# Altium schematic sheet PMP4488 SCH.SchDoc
size 431 x 279 mm; Date: Not shown in title block; ApprovedBy: Not shown in title block; CheckedBy: Not shown in title block; Author: Not shown in title block; CompanyName: Not shown in title block; Engineer: David Ji; Organization: Not shown in title block; Address1: Not shown in title block; Address2: Not shown in title block; Address3: Not shown in title block; Address4: Not shown in title block; DocumentNumber: 1; Revision: Use project parameter SCH_Rev; SheetNumber: 1; SheetTotal: 1; PageSetup: Record=PageOptions¦CenterHorizontal=True¦CenterVertical=True¦PrintScale=1.00¦XCorrection=1.00¦YCorrection=1.00¦PrintKind=0¦BorderSize=5000000¦LeftOffset=0¦BottomOffset=0¦Orientation=2¦PaperLength=1000¦PaperWidth=1000¦Scale=100¦PaperSource=15¦PrintQuality=600¦MediaType=1¦DitherType=10¦PaperKind=Letter¦PrintScaleMode=1
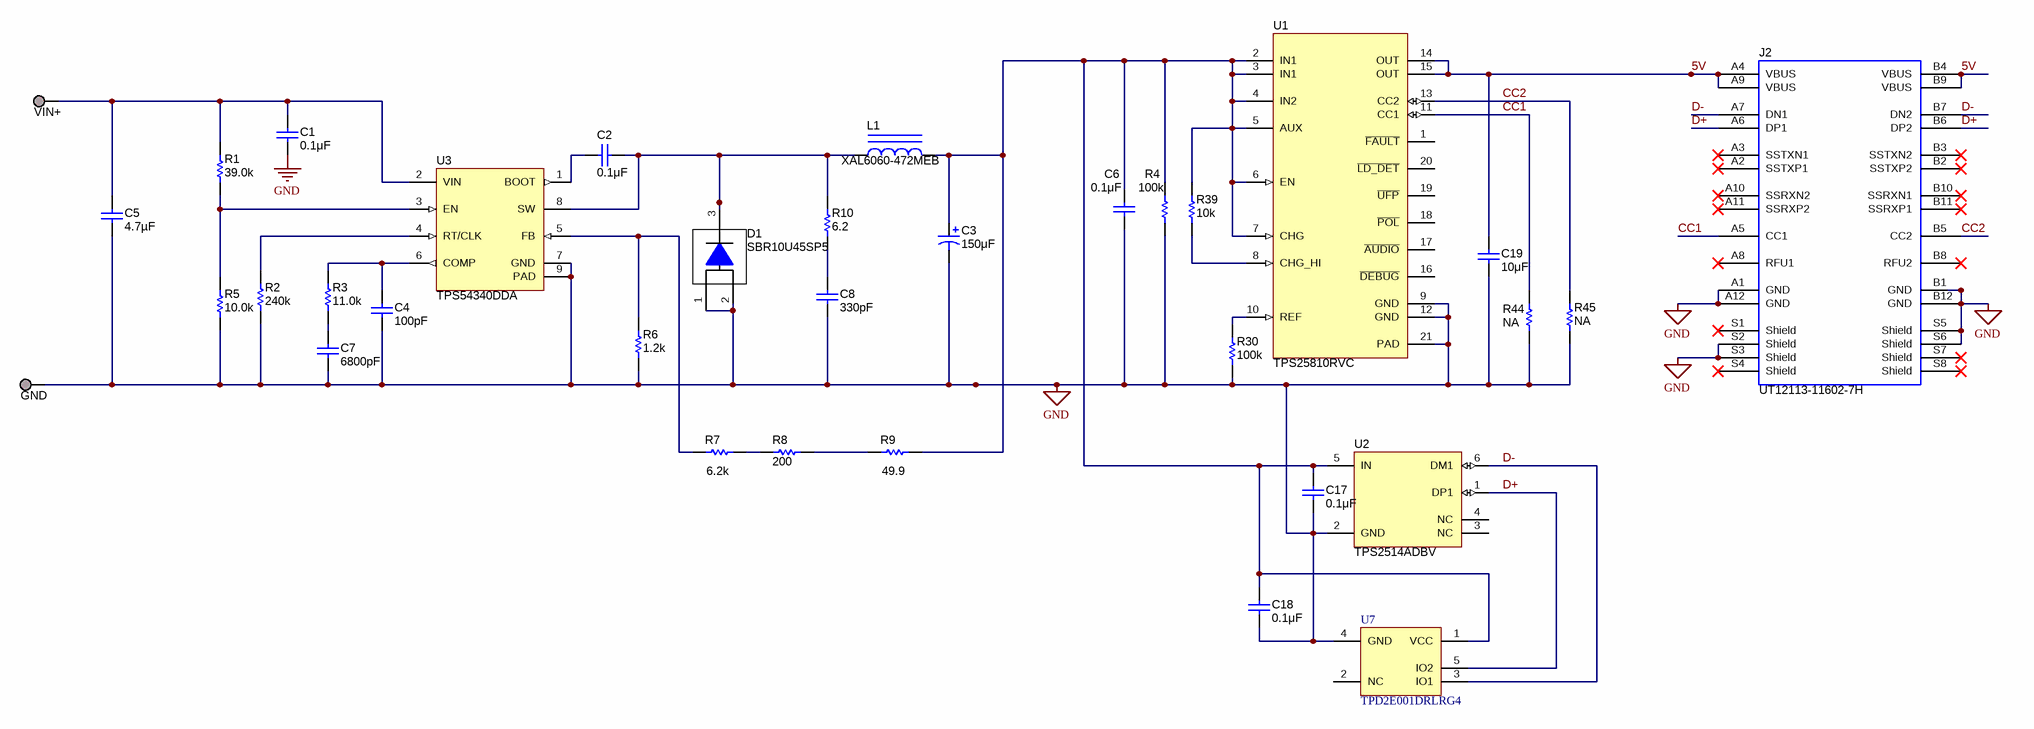
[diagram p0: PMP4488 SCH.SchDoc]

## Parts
C1  ValueDisplayed: 0.1μF  [0603]  (hidden comment: C0603C104K5RACTU)
C2  ValueDisplayed: 0.1μF  [0603]  (hidden comment: C0603C104K5RACTU)
C3  ValueDisplayed: 150μF  [CAPAE_SP-Cap_Standard]  (hidden comment: EEFCX0J181R)
C4  ValueDisplayed: 100pF  [0603]  (hidden comment: GRM1885C1H101JA01D)
C5  ValueDisplayed: 4.7µF  [1206]  (hidden comment: GRM319R61H475KA12)
C6  ValueDisplayed: 0.1μF  [0603]  (hidden comment: C1608X7R1E104K)
C7  ValueDisplayed: 6800pF  [0603]  (hidden comment: GRM188R71H682KA01D)
C8  ValueDisplayed: 330pF  [0603]  (hidden comment: GRM188R71H331KA01D)
C17  ValueDisplayed: 0.1μF  [0603]  (hidden comment: 06033C104JAT2A)
C18  ValueDisplayed: 0.1μF  [0603]  (hidden comment: 06033C104JAT2A)
C19  ValueDisplayed: 10μF  [0805_HV]  (hidden comment: C0805C106K8PACTU)
D1  SBR10U45SP5  [PowerDI5]
GND  Suggest using a net name here  [Keystone1502-2]  (value not drawn)
J2  UT12113-11602-7H  [Foxconn_UT12113-11602-7H]
L1  XAL6060-472MEB  [XAL6060]
R1  ValueDisplayed: 39.0k  [0603]  (hidden comment: RC0603FR-0739KL)
R2  ValueDisplayed: 240k  [0603]  (hidden comment: RC0603FR-07240KL)
R3  ValueDisplayed: 11.0k  [0603]  (hidden comment: RC0603FR-0711KL)
R4  ValueDisplayed: 100k  [0603]  (hidden comment: CRCW0603100KJNEA)
R5  ValueDisplayed: 10.0k  [0603]  (hidden comment: RC0603FR-0710KL)
R6  ValueDisplayed: 1.2k  [0603]  (hidden comment: CRCW06031K21FKEA)
R7  ValueDisplayed: 6.2k  [0603]  (hidden comment: RC0603FR-078K25L)
R8  ValueDisplayed: 200  [0603]  (hidden comment: RC0603FR-07200RL)
R9  ValueDisplayed: 49.9  [0603]  (hidden comment: RC0603FR-0749R9L)
R10  ValueDisplayed: 6.2  [0805_HV]  (hidden comment: CRCW08056R20JNEA)
R30  ValueDisplayed: 100k  [0603]  (hidden comment: CRCW0603100KFKEA)
R39  ValueDisplayed: 10k  [0603]  (hidden comment: CRCW060310K0JNEA)
R44  ValueDisplayed: NA  [0603]  (hidden comment: CRCW060310K0JNEA)
R45  ValueDisplayed: NA  [0603]  (hidden comment: CRCW060310K0JNEA)
U1  TPS25810RVC  [RVC0020A]
U2  TPS2514ADBV  [DBV0006A_N]
U3  TPS54340DDA  [DDA0008E_N]
U7  TPD2E001DRLRG4  [DRL0005A]
VIN+  Suggest using a net name here  [Keystone1502-2]  (value not drawn)

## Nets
GND: C1.2 C3.2(-) C4.2 C5.2 C6.2 C7.2 C8.1 C17.2 C18.2 C19.2 D1.1(A) D1.2(A) GND.1 J2.A1(GND) J2.A12(GND) J2.B1(GND) J2.B12(GND) J2.S2(Shield) J2.S3(Shield) J2.S5(Shield) J2.S6(Shield) R2.1 R4.1 R5.1 R6.1 R30.1 R44.1 R45.1 U1.9(GND) U1.12(GND) U1.21(PAD) U2.2(GND) U3.7(GND) U3.9(PAD) U7.4(GND)
5V: C19.1 J2.A4(VBUS) J2.A9(VBUS) J2.B4(VBUS) J2.B9(VBUS) U1.14(OUT) U1.15(OUT)
CC1: J2.A5(CC1) R44.2 U1.11(CC1)
CC2: J2.B5(CC2) R45.2 U1.13(CC2)
D+: J2.A6(DP1) J2.B6(DP2) U2.1(DP1) U7.5(IO2)
D-: J2.A7(DN1) J2.B7(DN2) U2.6(DM1) U7.3(IO1)
NetC1_1: C1.1 C5.1 R1.2 U3.2(VIN) VIN+.1
NetC2_1: C2.1 U3.1(BOOT)
NetC2_2: C2.2 D1.3(K) L1.1 R10.2 U3.8(SW)
NetC3_1: C3.1(+) C6.1 C17.1 C18.1 L1.2 R4.2 R9.2 R39.2 U1.2(IN1) U1.3(IN1) U1.4(IN2) U1.5(AUX) U1.6(EN) U1.7(CHG) U2.5(IN) U7.1(VCC)
NetC4_1: C4.1 R3.2 U3.6(COMP)
NetC7_1: C7.1 R3.1
NetC8_2: C8.2 R10.1
NetR1_1: R1.1 R5.2 U3.3(EN)
NetR2_2: R2.2 U3.4(RT/CLK)
NetR6_2: R6.2 R7.1 U3.5(FB)
NetR7_2: R7.2 R8.1
NetR8_2: R8.2 R9.1
NetR30_2: R30.2 U1.10(REF)
NetR39_1: R39.1 U1.8(CHG_HI)

Not connected (* = marked no-connect by the designer): J2 A2(SSTXP1)* A3(SSTXN1)* A8(RFU1)* A10(SSRXN2)* A11(SSRXP2)* B2(SSTXP2)* B3(SSTXN2)* B8(RFU2)* B10(SSRXN1)* B11(SSRXP1)* S1(Shield)* S4(Shield)* S7(Shield)* S8(Shield)*; U1 1(~{FAULT}) 16(~{DEBUG}) 17(~{AUDIO}) 18(~{POL}) 19(~{UFP}) 20(~{LD_DET}); U2 3(NC) 4(NC); U7 2(NC)

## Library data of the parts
C1 C2 = C0603C104K5RACTU: CAP, CERM, 0.1 μF, 50 V, +/- 10%, X7R, 0603; Manufacturer: Kemet; Polarized: N; CompType: Capacitor; Value: 0.1uF; U/M: EA; Cap_F: 0.0000001; Tolerance_%: 10; Value1: Unknown; VDC_V: 50; Value2: 50V; TaMin_C: -55; TaMax_C: 125
C3 = EEFCX0J181R: CAP, AL, 150 μF, 6.3 V, +/- 20%, 15 ohm, SMD; Manufacturer: Panasonic; Polarized: Y; CompType: Capacitor; Value: 180uF; U/M: EA; Cap_F: 0.00018; Tolerance_%: 20; Value1: 15 ohm; VDC_V: 6.3; Value2: 6.3V; ESR_ohm: 15; IRMS_A: 2.7; TaMin_C: -40; TaMax_C: 105
C4 = GRM1885C1H101JA01D: CAP, CERM, 100 pF, 50 V, +/- 5%, C0G/NP0, 0603; Manufacturer: MuRata; Polarized: N; CompType: Capacitor; Value: 100pF; U/M: EA; Cap_F: 0.0000000001; Tolerance_%: 5; Value1: Unknown; VDC_V: 50; Value2: 50V; TaMin_C: -55; TaMax_C: 125
C5 = GRM319R61H475KA12: CAP, CERM, 4.7 µF, 50 V, +/- 10%, X5R, 1206; Manufacturer: MuRata; Polarized: N; CompType: Capacitor; Value: 4.7uF; U/M: EA; Cap_F: 0.0000047; Tolerance_%: 10; Value1: Unknown; VDC_V: 50; Value2: 50V; TaMin_C: -55; TaMax_C: 85
C6 = C1608X7R1E104K: CAP, CERM, 0.1 μF, 25 V, +/- 10%, X7R, 0603; Manufacturer: TDK; Polarized: N; CompType: Capacitor; Value: 0.1uF; U/M: EA; Cap_F: 0.0000001; Tolerance_%: 10; ESR_ohm: 0.017; Value1: 0.017 ohm; VDC_V: 25; Value2: 25V; TaMin_C: -55; TaMax_C: 125
C7 = GRM188R71H682KA01D: CAP, CERM, 6800 pF, 50 V, +/- 10%, X7R, 0603; Manufacturer: MuRata; Polarized: N; CompType: Capacitor; Value: 6800pF; U/M: EA; Cap_F: 0.0000000068; Tolerance_%: 10; Value1: Unknown; VDC_V: 50; Value2: 50V; TaMin_C: -55; TaMax_C: 125
C8 = GRM188R71H331KA01D: CAP, CERM, 330 pF, 50 V, +/- 10%, X7R, 0603; Manufacturer: MuRata; Polarized: N; CompType: Capacitor; Value: 330pF; U/M: EA; Cap_F: 0.00000000033; Tolerance_%: 10; Value1: Unknown; VDC_V: 50; Value2: 50V; TaMin_C: -55; TaMax_C: 125
C17 C18 = 06033C104JAT2A: CAP, CERM, 0.1 μF, 25 V, +/- 5%, X7R, 0603; Manufacturer: AVX; Polarized: N; CompType: Capacitor; Value: 0.1uF; U/M: EA; Cap_F: 0.0000001; Tolerance_%: 5; ESR_ohm: 0.05; Value1: 0.05 ohm; VDC_V: 25; Value2: 25V; TaMin_C: -55; TaMax_C: 125
C19 = C0805C106K8PACTU: CAP, CERM, 10 μF, 10 V, +/- 10%, X5R, 0805; Manufacturer: Kemet; Polarized: N; CompType: Capacitor; Value: 10uF; U/M: EA; Cap_F: 0.00001; Tolerance_%: 10; ESR_ohm: 0.003; Value1: 0.003 ohm; Value2: 10V; IRMS_A: 11.43; TaMin_C: -55; TaMax_C: 85; Cap_Case: 0805
D1 = SBR10U45SP5: Diode, Super Barrier Rectifier, 45 V, 10 A, PowerDI5; Manufacturer: Diodes Inc.; SymbolCreator: a0412235; U/M: EA; Vf_V: 0.47; Value: 45V; Value1: 10A; Value2: 0.47V; Io_A: 10; Vr_V: 45; TJmax_C: 150
GND VIN+ = 1502-2: Terminal, Turret, TH, Double; Manufacturer: Keystone; CompType: Turret Terminal; U/M: EA
J2 = UT12113-11602-7H: Connector, Receptacle, USB TYPE C, R/A, SMT; Manufacturer: Foxconn; SymbolCreator: Altium; U/M: EA
L1 = XAL6060-472MEB: Inductor, Shielded, Composite, 4.7 µH, 10.5 A, 0.015 ohm, SMD; Manufacturer: Coilcraft; Value: 4.7uH; Ind_H: 4.7E-6; ValueDisplayed: 4.7µH; Imax_A: 10.5; Irms: 12.3A @ 40C rise; Isat: 10.5A @ 30% inductance drop; DCR_ohm: 0.015; Value2: 10.5A
R1 = RC0603FR-0739KL: RES, 39.0 k, 1%, 0.1 W, 0603; Manufacturer: Yageo America; CompType: Resistor; Value: 39.0k; Res_ohm: 39000; Value_Code: 39k0; Tolerance_%: 1; Power_W: 0.1; Value2: 0.1W; VDC_V: 150; TempCo: 200 ppm/C; U/M: EA
R2 = RC0603FR-07240KL: RES, 240 k, 1%, 0.1 W, 0603; Manufacturer: Yageo America; CompType: Resistor; Value: 240k; Res_ohm: 240000; Tolerance_%: 1; Power_W: 0.1; Value2: 0.1W; VDC_V: 150; TempCo: 200 ppm/C; U/M: EA
R3 = RC0603FR-0711KL: RES, 11.0 k, 1%, 0.1 W, 0603; Manufacturer: Yageo America; CompType: Resistor; Value: 11.0k; Res_ohm: 11000; Value_Code: 11k0; Tolerance_%: 1; Power_W: 0.1; Value2: 0.1W; VDC_V: 150; TempCo: 200 ppm/C; EIA_Code: E96; U/M: EA
R4 = CRCW0603100KJNEA: RES, 100 k, 5%, 0.1 W, 0603; Manufacturer: Vishay-Dale; CompType: Resistor; Value: 100k; Res_ohm: 100000; Tolerance_%: 5; Power_W: 0.1; Value2: 0.1W; VDC_V: 75; TempCo: 200 ppm/C; EIA_Code: E24; U/M: EA
R5 = RC0603FR-0710KL: RES, 10.0 k, 1%, 0.1 W, 0603; Manufacturer: Yageo America; CompType: Resistor; Value: 10.0k; Res_ohm: 10000; Value_Code: 10k0; Tolerance_%: 1; Power_W: 0.1; Value2: 0.1W; VDC_V: 150; TempCo: 200 ppm/C; EIA_Code: E96; U/M: EA
R6 = CRCW06031K21FKEA: RES, 1.21 k, 1%, 0.1 W, 0603; Manufacturer: Vishay-Dale; CompType: Resistor; Value: 1.21k; Res_ohm: 1210; Value_Code: 1k21; Tolerance_%: 1; Power_W: 0.1; Value2: 0.1W; VDC_V: 75; TempCo: 100 ppm/C; EIA_Code: E96; U/M: EA
R7 = RC0603FR-078K25L: RES, 8.25 k, 1%, 0.1 W, 0603; Manufacturer: Yageo America; CompType: Resistor; Value: 8.25k; Res_ohm: 8250; Value_Code: 8k25; Tolerance_%: 1; Power_W: 0.1; Value2: 0.1W; VDC_V: 150; TempCo: 200 ppm/C; EIA_Code: E96; U/M: EA
R8 = RC0603FR-07200RL: RES, 200, 1%, 0.1 W, 0603; Manufacturer: Yageo America; CompType: Resistor; Value: 200; Value_Code: 200R; Tolerance_%: 1; Power_W: 0.1; Value2: 0.1W; VDC_V: 150; TempCo: 200 ppm/C; EIA_Code: E96; U/M: EA
R9 = RC0603FR-0749R9L: RES, 49.9, 1%, 0.1 W, 0603; Manufacturer: Yageo America; CompType: Resistor; Value: 49.9; Value_Code: 49R9; Tolerance_%: 1; Power_W: 0.1; Value2: 0.1W; VDC_V: 150; TempCo: 200 ppm/C; EIA_Code: E96; U/M: EA
R10 = CRCW08056R20JNEA: RES, 6.2, 5%, 0.125 W, 0805; Manufacturer: Vishay-Dale; CompType: Resistor; Value: 6.2; Value_Code: 6R20; Tolerance_%: 5; Power_W: 0.125; Value2: 0.125W; VDC_V: 150; TempCo: 200 ppm/C; EIA_Code: E24; U/M: EA
R30 = CRCW0603100KFKEA: RES, 100 k, 1%, 0.1 W, 0603; Manufacturer: Vishay-Dale; CompType: Resistor; Value: 100k; Res_ohm: 100000; Tolerance_%: 1; Power_W: 0.1; Value2: 0.1W; VDC_V: 75; TempCo: 100 ppm/C; EIA_Code: E96; U/M: EA
R39 R44 R45 = CRCW060310K0JNEA: RES, 10 k, 5%, 0.1 W, 0603; Manufacturer: Vishay-Dale; CompType: Resistor; Value: 10k; Res_ohm: 10000; Value_Code: 10k0; Tolerance_%: 5; Power_W: 0.1; Value2: 0.1W; VDC_V: 75; TempCo: 200 ppm/C; EIA_Code: E24; U/M: EA
U1 = TPS25810RVC: USB Type-C DFP Controller and Power Switch with Load Detection, RVC0020A; Manufacturer: Texas Instruments; SymbolCreator: Altium; CompType: IC; U/M: EA
U2 = TPS2514ADBV: USB Dedicated Charging Port Controller, DBV0006A; Manufacturer: Texas Instruments; SymbolCreator: a0411947; CompType: IC; U/M: EA
U3 = TPS54340DDA: 42 V Input, 3.5 A, Step Down DC-DC Converter with Eco-mode, DDA0008E; Manufacturer: Texas Instruments; SymbolCreator: a0411947; CompType: IC; U/M: EA
U7 = TPD2E001DRLRG4: Low-Capacitance + / - 15 kV ESD-Protection Array for High-Speed Data Interfaces, 2 Channels, -40 to +85 degC, 5-pin SOT (DRL), Green (RoHS & no Sb/Br); Manufacturer: Texas Instruments; Alternate Manufacturer: None; Alternate PartNumber: Equivalent; Breakdown Voltage(Min)(V): 11; IEC 61000-4-2 Air-Gap(+/- kV): 15; IEC 61000-4-2 Contact(+/- kV): 8; IO Capacitance(Typ)(pF): 1.5; IO Leakage Current(nA): 1; SubFamily: ESD Solution; USB High Speed: TRUE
